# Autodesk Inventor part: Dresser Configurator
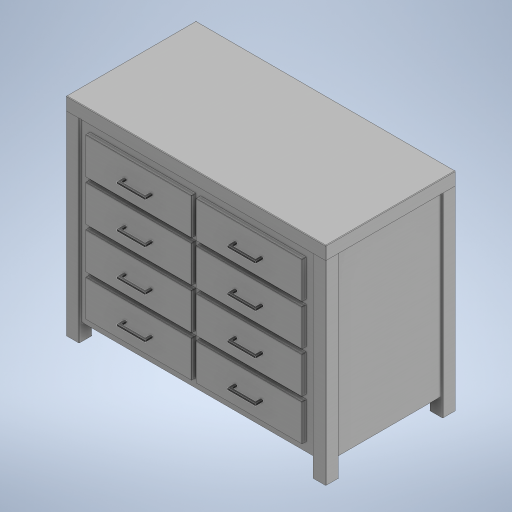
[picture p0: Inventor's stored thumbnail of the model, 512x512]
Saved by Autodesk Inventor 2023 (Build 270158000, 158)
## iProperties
Company: Jay's Dressers
RuleStatus: InUse
Created: 2022-06
Part Number: Dresser Configurator
Material: Generic
Document SubType Name: Modeling
Designer: Admin
Density: 1 g/cm^3
Appearance: Default
dresserHeight: 48.000 in
topThickness: 3.000 in
dresserWidth: 60.000 in
drawerRows: 4.000 ul
drawerColumns: 2.000 ul
panelThickness: 1.000 in
drawerHeight: 6.500 in
drawerVerticalOffset: 3.000 in
drawerWidth: 22.500 in
drawerHorizontalOffset: 3.000 in
dresserDepth: 30.000 in
Author: Cadflair
Title: Dresser Configurator
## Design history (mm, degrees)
sketch "Base Sketch"
  geometry: L1 (-762, 381)-(762, 381); L2 (762, 381)-(762, -381); L3 (762, -381)-(-762, -381); L4 (-762, -381)-(-762, 381); L5 (-762, 381)-(762, -381); L6 (762, 381)-(-762, -381); L7 (762, 381)-(685.8, 381); L8 (685.8, 381)-(685.8, 304.8); L9 (685.8, 304.8)-(762, 304.8); L10 (762, 304.8)-(762, 381); L11 (-762, 381)-(-685.8, 381); L12 (-685.8, 381)-(-685.8, 304.8); L13 (-685.8, 304.8)-(-762, 304.8); L14 (-762, 304.8)-(-762, 381); L15 (-762, -381)-(-685.8, -381); L16 (-685.8, -381)-(-685.8, -304.8); L17 (-685.8, -304.8)-(-762, -304.8); L18 (-762, -304.8)-(-762, -381); L19 (762, -381)-(685.8, -381); L20 (685.8, -381)-(685.8, -304.8); L21 (685.8, -304.8)-(762, -304.8); L22 (762, -304.8)-(762, -381); 1 further point
  constraints: 44 end point, 10 parallel, 5 equal length, 5 horizontal, 5 perpendicular, 2 midpoint, 1 point on line
  dimensions: "dresserWidth" = 1524 distance of L2.end L3.end; "dresserDepth" = 762 distance of L1.end L2.end; "legDepth" = 76.2 distance of L7.end L8.end; "legWidth" = 76.2 distance of L8.end L9.end
node "Top Plane"
sketch "Top Sketch"
  geometry: L1 (762, 381)-(762, -381) reference; L2 (762, -381)-(-762, -381) reference; L3 (-762, 381)-(762, 381) reference; L4 (-762, -381)-(-762, 381) reference; 1 further point
node "Front Plane"
sketch "Front Panel Sketch"
  geometry: L1 (685.8, 101.6)-(-685.8, 101.6); L2 (-685.8, 101.6)-(-685.8, 1143); L3 (-685.8, 1143)-(685.8, 1143); L4 (685.8, 1143)-(685.8, 101.6); L5 (762, 1219.2)-(-762, 1219.2) reference; 8 further points
  constraints: 8 end point, 3 vertical alignment, 2 parallel, 1 horizontal, 1 midpoint, 1 perpendicular
  dimensions: "legExposure" = 101.6 distance from line of point (0, 0) L1; "d7" = 76.2 distance between parallel lines of L3 L5 (= topThickness); "frontPanelWidth" = 1371.6 distance of L1.start L1.end (derived); "frontPanelHeight" = 1041.4 distance of L1.end L2.end (derived)
sketch "Drawer Cut Sketch"
  geometry: L1 (-685.8, 101.6)-(-685.8, 1143) reference; L2 (685.8, 101.6)-(-685.8, 101.6) reference; L3 (-609.6, 177.8)-(-38.1, 177.8); L4 (-38.1, 177.8)-(-38.1, 342.9); L5 (-38.1, 342.9)-(-609.6, 342.9); L6 (-609.6, 342.9)-(-609.6, 177.8); L7 (-12.7, 368.3)-(-12.7, 152.4); L8 (-12.7, 152.4)-(-635, 152.4); L9 (-635, 152.4)-(-635, 368.3); L10 (-635, 368.3)-(-12.7, 368.3); 1 further point
  constraints: 16 end point, 4 parallel, 2 perpendicular, 1 horizontal, 3 other
  dimensions: "drawerHeight" = 165.1 distance of L5.end L3.start (computed from drawerRows, drawerHorizontalOffset, frontPanelHeight); "drawerVerticalOffset" = 76.2 distance between parallel lines of L6 L1; "drawerWidth" = 571.5 distance of L4.end L5.end (computed from drawerColumns, drawerVerticalOffset, frontPanelWidth); "drawerHorizontalOffset" = 76.2 distance between parallel lines of L3 L2; "d37" = 25.4 distance between parallel lines of L4 L7
node "Back Plane"
sketch "Back Panel Sketch"
  geometry: L1 (685.8, 1143)-(685.8, 101.6) reference; L2 (-685.8, 1143)-(685.8, 1143) reference; L3 (685.8, 101.6)-(-685.8, 101.6) reference; L4 (-685.8, 101.6)-(-685.8, 1143) reference; 1 further point
node "Right Plane"
node "Left Plane"
sketch "Right Panel Sketch"
  geometry: L1 (1143, -342.9)-(101.6, -342.9) reference; L2 (1143, 342.9)-(101.6, 342.9) reference; L3 (1143, 342.9)-(1143, -342.9); L4 (101.6, -342.9)-(101.6, 342.9); 1 further point
  constraints: 4 end point, 1 parallel, 1 perpendicular
sketch "Left Panel Sketch"
  geometry: L1 (101.6, -342.9)-(1143, -342.9) reference; L2 (101.6, 342.9)-(1143, 342.9) reference; L3 (101.6, -342.9)-(101.6, 342.9); L4 (1143, -342.9)-(1143, 342.9); 1 further point
  constraints: 4 end point, 1 perpendicular, 1 vertical
extrude "Front Panel Extrusion" new body sketch "Front Panel Sketch" distance "d17" = 25.4 (= panelThickness); taper "d18" = 0 deg
extrude "Right Panel Extrusion" join sketch "Right Panel Sketch" distance "d19" = 25.4 (= panelThickness); taper "d20" = 0 deg
extrude "Left Panel Extrusion" join sketch "Left Panel Sketch" distance "d21" = 25.4 (= panelThickness); taper "d22" = 0 deg
extrude "Rear Panel Extrusion" join sketch "Back Panel Sketch" distance "d23" = 25.4 (= panelThickness); taper "d24" = 0 deg
node "Bottom Panel Plane"
sketch "Sketch12"
  geometry: L1 (1409.7, 685.8)-(-38.1, 685.8); L2 (-38.1, 685.8)-(-38.1, 0); L3 (-38.1, 0)-(1409.7, 0); L4 (1409.7, 0)-(1409.7, 685.8); L5 (0, 685.8)-(1371.6, 685.8) reference; L6 (1409.7, 685.8)-(1409.7, 0) reference; L7 (0, 0)-(1371.6, 0) reference; L8 (-38.1, 685.8)-(-38.1, 0) reference; 1 further point
  constraints: 8 end point, 4 collinear, 2 parallel, 1 horizontal, 1 perpendicular
extrude "Bottom Panel Extrusion" join sketch "Sketch12" distance "d76" = 25.4 (derived); taper "d77" = 0 deg
extrude "Drawer Cutout Extrusion" cut sketch "Drawer Cut Sketch" stored distance "d25" = 25.4 (= panelThickness); taper "d26" = 0 deg
extrude "Drawer Face Extrusion" join sketch "Drawer Cut Sketch" stored distance "d38" = 25.4 (= panelThickness); taper "d39" = 0 deg
fillet "Drawer Fillet1" dims "filletRadius" = 1.905
pattern_linear "Drawer Rectangular Pattern" dims "d29" = 647.7 (= drawerWidth + drawerVerticalOffset), "d32" = 241.3 (= drawerHeight + drawerHorizontalOffset)
node "Drawer Mid Plane1"
sketch "Sketch11"
  geometry: L1 (0, -1.905)-(618.49, -1.905) reference; L2 (226.695, -1.905)-(391.795, -1.905); L3 (391.795, -1.905)-(391.795, -46.355); L4 (391.795, -46.355)-(226.695, -46.355); L5 (226.695, -46.355)-(226.695, -1.905); L6 (239.395, -1.905)-(239.395, -33.655); L7 (239.395, -33.655)-(379.095, -33.655); L8 (379.095, -33.655)-(379.095, -1.905); 6 further points
  constraints: 14 end point, 3 perpendicular, 2 midpoint, 2 parallel, 2 point on line, 1 horizontal, 1 vertical
  dimensions: "d68" = 44.45 distance of L4.end L2.start; "d69" = 165.1 distance of L3.end L4.end; "d70" = 12.7 distance between parallel lines of L6 L5; "d71" = 12.7 distance between parallel lines of L3 L8 (= d70); "d72" = 12.7 distance between parallel lines of L7 L4 (= d70)
extrude "Square Handle Extrusion" new body sketch "Sketch11" stored distance "d73" = 12.7; taper "d74" = 0 deg
node "Drawer Mid Plane2"
sketch "Sketch10"
  geometry: L1 (-1.905, 0)-(-1.905, 212.09) reference; L2 (-1.905, 110.807)-(-1.905, 106.045); L3 (-1.905, 106.045)-(-40.005, 106.045); L4 (-27.305, 131.445)-(-24.13, 131.445); L5 (-24.13, 131.445)-(-24.13, 110.807); L6 (-24.13, 110.807)-(-1.905, 110.807); A1 r 31.75 centre (-8.255, 106.045) between (-27.305, 131.445) and (-40.005, 106.045); 2 further points
  constraints: 10 end point, 3 perpendicular, 2 point on circle, 1 centre point, 1 midpoint, 1 parallel, 1 point on line, 1 vertical
  dimensions: "d61" = 38.1 distance of L2.end L3.end; "d62" = 3.175 distance of L4.start L4.end; "d63" = 22.225 distance of L5.end L2.start; "d64" = 9.525 diameter of L6 L3; "d65" = 50.8 diameter of L4 L3
revolve "Round Knob Revolution1" sketch "Sketch10" stored, may be unused: angle "d66" = 90 deg
fillet "Round Knob Fillet" dims "d67" = 0.635
sketch "Sketch8"
  geometry: L1 (-1.905, 118.745)-(-1.905, 93.345); L2 (-1.905, 93.345)-(-27.305, 93.345); L3 (-1.905, 0)-(-1.905, 212.09) reference; A1 r 25.4 centre (-1.905, 93.345) between (-1.905, 118.745) and (-27.305, 93.345); 2 further points
  constraints: 4 end point, 2 midpoint, 2 perpendicular, 2 point on circle, 1 centre point, 1 point on line, 1 vertical
  dimensions: "d43" = 25.4 distance of L1.end L2.end
extrude "Bin Pull Exrusion" new body sketch "Sketch8" stored distance "d44" = 127; taper "d45" = 0 deg
fillet "Bin Pull Fillet" dims "d46" = 25.4
sketch "Sketch9"
  geometry: L1 (127, 0)-(0, 0) reference; L2 (101.6, 25.4)-(25.4, 25.4) reference; L3 (-2.998, -3.175)-(129.998, -3.175); L4 (101.6, 28.575)-(25.4, 28.575); L5 (0, 0)-(-3.175, 0); L6 (127, 0)-(130.175, 0); A1 r 25.4 centre (25.4, 0) between (25.4, 25.4) and (0, 0) reference; A2 r 25.4 centre (101.6, 0) between (127, 0) and (101.6, 25.4) reference; A3 r 28.575 centre (25.4, 0) between (25.4, 28.575) and (-2.998, -3.175); A4 r 28.575 centre (101.6, 0) between (129.998, -3.175) and (101.6, 28.575); 1 further point
  constraints: 8 end point, 6 point on circle, 2 centre point, 2 horizontal, 3 other
  dimensions: "d47" = 3.175 distance between parallel lines of L2 L4
extrude "Bin Pull Exrusion2" join sketch "Sketch9" distance "d48" = 3.175; taper "d49" = 0 deg
extrude "Top Extrusion" join sketch "Top Sketch" distance "d33" = 76.2 (= topThickness); taper "d34" = 0 deg
fillet "Fillet3" dims "topFilletRadius" = 3.175
extrude "Leg Extrusion" new body sketch "Base Sketch" stored distance "d35" = 76.2 (derived); taper "d36" = 0 deg
fillet "Leg Fillet" dims "legFilletRadius" = 3.175
node "Panels Solid"
pattern_linear "Handle Rectangular Pattern" dims "d52" = 647.7 (= d29), "d55" = 241.3 (= d32)
node "Leg Solid"
node "Bin Pull Solid"
node "Projected Loop1"
node "Round Knob Solid"
node "Square Handle Solid"
other parameters: "dresserHeight" = 1219.2, "topThickness" = 76.2 [user parameter; used in 2 equation terms], "d5" = 342.9 (= 0.5 x dresserDepth - 0.5 x legDepth), "drawerRows" = 4 [user parameter; used in 2 equation terms], "drawerColumns" = 2 [user parameter; used in 2 equation terms], "panelThickness" = 25.4 [user parameter; used in 6 equation terms], "d14" = -342.9 (= -0.5 x dresserDepth + 0.5 x legDepth), "d15" = 723.9 (= 0.5 x dresserWidth - 0.5 x legWidth), "d16" = -723.9 (= -0.5 x dresserWidth + 0.5 x legWidth), "d75" = -25.4
